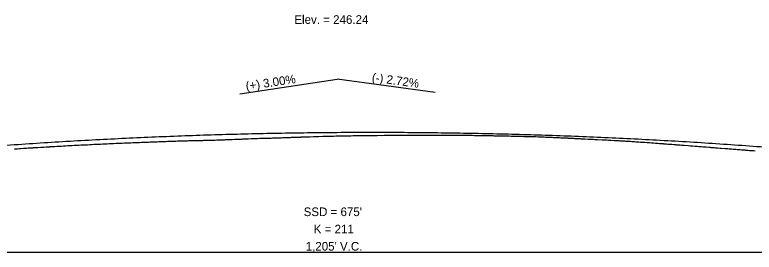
# Model space of a CAD drawing. Extents: x 1838386 to 1955906, y 719739 to 834437.
# Drawn here: x 1889991 to 1890591, y 826224 to 826417 of the extents above; entities that cross this region are included whole.
import ezdxf

# ---------------------------------------------------------------- set-up
doc = ezdxf.new("R2010")
doc.units = 0
for name, color, linetype in [('RD_DDB_GradeTX', 7, 'Continuous'), ('RD_DDB_Profile_EX', 7, 'Continuous'), ('RD_DDB_Profile_Lbl', 7, 'Continuous'), ('RD_DDB_Profile_PR', 7, 'Continuous'), ('RD_DDB_VCLbl', 7, 'Continuous')]:
    doc.layers.add(name, color=color, linetype=linetype)

msp = doc.modelspace()

# ---------------------------------------------------------------- linework, layer by layer
at = {"layer": 'RD_DDB_GradeTX'}
for p in [(1890173.96, 826352.46), (1890332.35, 826353.54)]:
    msp.add_line(p, (1890253.08, 826364.32), dxfattribs=at)
at = {"layer": 'RD_DDB_Profile_EX'}
for points in [[(1890027.2, 826310.09), (1890027.5, 826310.1), (1890029.04, 826310.16), (1890030.99, 826310.3), (1890032.55, 826310.36), (1890034.5, 826310.5), (1890036.11, 826310.56), (1890038, 826310.7), (1890039.63, 826310.75), (1890041.52, 826310.88), (1890043.18, 826310.92), (1890045.02, 826311.06), (1890046.7, 826311.11), (1890048.52, 826311.24), (1890050.24, 826311.28), (1890052.15, 826311.42), (1890053.78, 826311.47), (1890055.55, 826311.59), (1890057.31, 826311.63), (1890059.28, 826311.76), (1890060.85, 826311.8), (1890062.56, 826311.9), (1890064.38, 826311.96), (1890066.4, 826312.09), (1890067.92, 826312.13), (1890069.64, 826312.24), (1890071.45, 826312.28), (1890073.53, 826312.4), (1890075, 826312.44), (1890076.78, 826312.55), (1890078.52, 826312.58), (1890080.37, 826312.68), (1890080.67, 826312.7), (1890082.08, 826312.74), (1890083.6, 826312.82), (1890083.91, 826312.83), (1890085.59, 826312.87), (1890087.1, 826312.96), (1890087.44, 826312.97), (1890087.8, 826312.99), (1890089.15, 826313.02), (1890091.04, 826313.12), (1890092.66, 826313.16), (1890094.12, 826313.23), (1890094.51, 826313.24), (1890094.94, 826313.26), (1890096.24, 826313.3), (1890098.19, 826313.4), (1890099.74, 826313.43), (1890101.13, 826313.5), (1890101.58, 826313.51), (1890102.09, 826313.54), (1890103.32, 826313.57), (1890104.64, 826313.63), (1890105.34, 826313.66), (1890106.82, 826313.69), (1890108.14, 826313.76), (1890108.66, 826313.77), (1890109.23, 826313.8), (1890110.4, 826313.83), (1890111.66, 826313.89), (1890112.48, 826313.91), (1890113.89, 826313.94), (1890115.16, 826314), (1890116.35, 826314.04), (1890117.45, 826314.06), (1890118.65, 826314.12), (1890119.62, 826314.15), (1890120.96, 826314.18), (1890122.17, 826314.23), (1890123.45, 826314.28), (1890125.68, 826314.34), (1890126.75, 826314.37), (1890127.98, 826314.39), (1890129.19, 826314.44), (1890129.75, 826314.45), (1890130.34, 826314.48), (1890131.55, 826314.49), (1890132.7, 826314.55), (1890133.88, 826314.58), (1890135.05, 826314.59), (1890136.22, 826314.64), (1890136.85, 826314.64), (1890137.6, 826314.67), (1890138.7, 826314.68), (1890139.71, 826314.71), (1890141.01, 826314.73), (1890142.12, 826314.72), (1890143.25, 826314.76), (1890144, 826314.77), (1890144.83, 826314.81), (1890145.76, 826314.82), (1890146.73, 826314.86), (1890148.11, 826314.9), (1890150.27, 826314.96), (1890151.07, 826314.98), (1890151.96, 826315.01), (1890152.94, 826315.03), (1890153.73, 826315.06), (1890155.26, 826315.12), (1890156.02, 826315.13)], [(1890156.02, 826315.13), (1890157.23, 826315.18), (1890158.03, 826315.2), (1890158.85, 826315.24), (1890160.13, 826315.27), (1890160.77, 826315.29), (1890161.62, 826315.31), (1890162.42, 826315.36), (1890163.24, 826315.39), (1890164.26, 826315.43), (1890165.99, 826315.5), (1890166.32, 826315.51), (1890167.45, 826315.55), (1890167.77, 826315.56), (1890169.57, 826315.64), (1890170.49, 826315.67), (1890171.88, 826315.73), (1890172.88, 826315.75), (1890173.47, 826315.79), (1890174.93, 826315.85), (1890175.58, 826315.87), (1890176.34, 826315.91), (1890177.87, 826315.97), (1890178.2, 826315.98), (1890180.65, 826316.07), (1890183.14, 826316.18), (1890183.83, 826316.2), (1890185.6, 826316.25), (1890187.69, 826316.33), (1890188.03, 826316.34), (1890188.39, 826316.35), (1890190.34, 826316.43), (1890191.32, 826316.47), (1890193.15, 826316.53), (1890194.55, 826316.56), (1890196.08, 826316.59), (1890197.55, 826316.61), (1890198.13, 826316.64), (1890199.33, 826316.67), (1890200.49, 826316.71), (1890201.67, 826316.76), (1890202.83, 826316.8), (1890203.51, 826316.81), (1890205.23, 826316.89), (1890206.34, 826316.93), (1890207.75, 826316.95), (1890208.79, 826317.02), (1890209.84, 826317.05), (1890210.83, 826317.06), (1890212.38, 826317.13), (1890213.35, 826317.16), (1890214.96, 826317.18), (1890215.94, 826317.25), (1890216.86, 826317.28), (1890218.09, 826317.29), (1890219.52, 826317.38), (1890220.36, 826317.4), (1890223.08, 826317.49), (1890223.48, 826317.5), (1890223.87, 826317.51), (1890225.25, 826317.51), (1890226.65, 826317.61), (1890227.39, 826317.63), (1890230.2, 826317.71), (1890230.89, 826317.73), (1890233.78, 826317.82), (1890234.39, 826317.84), (1890237.34, 826317.94), (1890237.9, 826317.95), (1890241.4, 826318.05), (1890242.94, 826318.06), (1890244.91, 826318.16), (1890246.47, 826318.16), (1890248.42, 826318.25), (1890250.01, 826318.24), (1890251.92, 826318.32), (1890253.54, 826318.32), (1890255.43, 826318.41), (1890257.09, 826318.4), (1890258.94, 826318.48), (1890260.62, 826318.48), (1890262.44, 826318.55), (1890264.17, 826318.53), (1890265.96, 826318.61), (1890267.71, 826318.59), (1890269.5, 826318.66), (1890271.25, 826318.64), (1890273.05, 826318.71), (1890276.65, 826318.76), (1890278.26, 826318.74), (1890279.98, 826318.8), (1890281.8, 826318.76), (1890283.82, 826318.84), (1890285.36, 826318.81), (1890287.08, 826318.86), (1890288.89, 826318.83), (1890291, 826318.9), (1890292.46, 826318.87), (1890294.27, 826318.93), (1890295.92, 826318.89), (1890297.86, 826318.94)], [(1890297.86, 826318.94), (1890299.46, 826318.91), (1890301.46, 826318.97), (1890301.84, 826318.96), (1890303, 826318.93), (1890305, 826318.98), (1890306.51, 826318.94), (1890307.36, 826318.97), (1890308.57, 826318.99), (1890310.03, 826318.95), (1890311.47, 826319), (1890311.79, 826319), (1890312.12, 826319), (1890312.89, 826318.99), (1890313.55, 826318.97), (1890314.94, 826319.01), (1890315.31, 826319.01), (1890315.67, 826319.01), (1890317.01, 826318.98), (1890318.91, 826319.02), (1890320.5, 826318.98), (1890321.92, 826319.02), (1890322.33, 826319.02), (1890322.78, 826319.02), (1890324.05, 826318.98), (1890325.41, 826319.02), (1890326, 826319.02), (1890327.53, 826318.99), (1890328.91, 826319.02), (1890329.47, 826319.02), (1890329.87, 826319.02), (1890331.09, 826318.99), (1890332.42, 826319.02), (1890332.76, 826319.02), (1890333.08, 826319.02), (1890334.51, 826318.98), (1890335, 826318.99), (1890335.92, 826319.01), (1890336.26, 826319.01), (1890336.61, 826319.01), (1890338.02, 826318.98), (1890339.42, 826319), (1890339.79, 826319), (1890340.16, 826319), (1890340.52, 826319), (1890341.55, 826318.98), (1890342.93, 826319.01), (1890343.31, 826319), (1890343.68, 826319), (1890345.07, 826318.97), (1890346.05, 826318.99), (1890346.44, 826319), (1890346.83, 826318.99), (1890347.22, 826319), (1890348.53, 826318.96), (1890350.43, 826318.99), (1890351.58, 826318.96), (1890352.03, 826318.95), (1890353.48, 826318.97), (1890353.86, 826318.97), (1890354.28, 826318.97), (1890355.57, 826318.94), (1890357.47, 826318.95), (1890359.06, 826318.9), (1890360.52, 826318.91), (1890361.22, 826318.9), (1890362.63, 826318.88), (1890364.5, 826318.85), (1890366.04, 826318.79), (1890368.16, 826318.8), (1890369.56, 826318.74), (1890371.5, 826318.76), (1890373.07, 826318.69), (1890373.68, 826318.69), (1890374.66, 826318.69), (1890374.98, 826318.69), (1890378.49, 826318.63), (1890379.21, 826318.6), (1890380.03, 826318.57), (1890381.74, 826318.58), (1890383.54, 826318.51), (1890384.74, 826318.51), (1890385.47, 826318.51), (1890387.06, 826318.44), (1890388.85, 826318.43), (1890390.26, 826318.38), (1890390.58, 826318.36), (1890392.42, 826318.37), (1890394.09, 826318.29), (1890395.97, 826318.28), (1890399.1, 826318.19), (1890399.5, 826318.18), (1890401.32, 826318.12), (1890403.09, 826318.1), (1890404.56, 826318.04), (1890405.97, 826318.03), (1890406.31, 826318.01), (1890406.84, 826318), (1890408.08, 826317.93), (1890409.45, 826317.92), (1890409.83, 826317.9)], [(1890409.83, 826317.9), (1890410.23, 826317.9), (1890411.59, 826317.84), (1890412.37, 826317.82), (1890412.9, 826317.81), (1890413.35, 826317.79), (1890413.82, 826317.78), (1890416.38, 826317.69), (1890417.39, 826317.66), (1890417.9, 826317.63), (1890418.53, 826317.6), (1890419.53, 826317.58), (1890420.27, 826317.54), (1890420.98, 826317.51), (1890422.11, 826317.45), (1890423.42, 826317.41), (1890423.89, 826317.38), (1890424.56, 826317.37), (1890425.57, 826317.33), (1890426.44, 826317.3), (1890427.32, 826317.26), (1890428.15, 826317.23), (1890428.95, 826317.2), (1890430.05, 826317.16), (1890431.75, 826317.08), (1890432.58, 826317.03), (1890433.38, 826317.01), (1890434.48, 826316.95), (1890435.34, 826316.91), (1890436.11, 826316.87), (1890436.8, 826316.84), (1890438.97, 826316.76), (1890440, 826316.71), (1890440.31, 826316.69), (1890441.38, 826316.62), (1890442.55, 826316.58), (1890443.04, 826316.56), (1890443.46, 826316.54), (1890444.84, 826316.44), (1890445.53, 826316.41), (1890446.16, 826316.39), (1890447.16, 826316.34), (1890449.77, 826316.22), (1890450.09, 826316.2), (1890450.4, 826316.19), (1890451.06, 826316.15), (1890451.87, 826316.1), (1890453.39, 826316.05), (1890453.83, 826316.02), (1890456.59, 826315.87), (1890457.35, 826315.83), (1890458.87, 826315.73), (1890460.63, 826315.68), (1890462.11, 826315.61), (1890464.26, 826315.5), (1890467.88, 826315.31), (1890469.32, 826315.21), (1890470.65, 826315.16), (1890471.09, 826315.13), (1890471.51, 826315.11), (1890473.17, 826315.02), (1890474.2, 826314.97), (1890474.63, 826314.94), (1890475.15, 826314.92), (1890477.61, 826314.79), (1890478.8, 826314.72), (1890480.79, 826314.61), (1890481.63, 826314.55), (1890482.4, 826314.51), (1890483.4, 826314.44), (1890484.28, 826314.4), (1890485.14, 826314.34), (1890486.12, 826314.29), (1890486.91, 826314.24), (1890487.75, 826314.2), (1890488.73, 826314.12), (1890489.75, 826314.07), (1890490.93, 826314), (1890492.19, 826313.89), (1890493.4, 826313.85), (1890493.92, 826313.82), (1890494.33, 826313.79), (1890495.27, 826313.71), (1890495.61, 826313.67), (1890497.06, 826313.61), (1890497.48, 826313.59), (1890497.84, 826313.56), (1890499.12, 826313.43), (1890501.09, 826313.33), (1890502.7, 826313.18), (1890504.39, 826313.11), (1890506.33, 826312.91), (1890508.07, 826312.83), (1890509.63, 826312.67), (1890511.26, 826312.58), (1890511.85, 826312.53), (1890513.14, 826312.41), (1890514.43, 826312.34), (1890514.93, 826312.3), (1890515.4, 826312.27), (1890517.38, 826312.12)], [(1889991.23, 826307.87), (1889991.85, 826307.92), (1889992.42, 826307.95), (1889993.7, 826308.01), (1889995.12, 826308.13), (1889995.51, 826308.16), (1889995.93, 826308.18), (1889998.36, 826308.35), (1889998.93, 826308.39), (1889999.44, 826308.42), (1890000.77, 826308.47), (1890002.25, 826308.6), (1890002.58, 826308.63), (1890002.94, 826308.65), (1890005.5, 826308.8), (1890006, 826308.83), (1890006.45, 826308.86), (1890007.84, 826308.92), (1890009.95, 826309.08), (1890012.62, 826309.23), (1890013.06, 826309.26), (1890013.46, 826309.28), (1890014.9, 826309.34), (1890016.96, 826309.5), (1890018.36, 826309.56), (1890019.73, 826309.66), (1890020.12, 826309.69), (1890020.48, 826309.71), (1890021.97, 826309.77), (1890023.99, 826309.91), (1890025.46, 826309.96), (1890026.86, 826310.06), (1890027.2, 826310.09)], [(1890517.38, 826312.12), (1890517.76, 826312.09), (1890518.36, 826312.03), (1890519.1, 826311.98), (1890520.23, 826311.87), (1890521.23, 826311.82), (1890521.93, 826311.75), (1890522.91, 826311.7), (1890523.66, 826311.63), (1890524.56, 826311.57), (1890526.5, 826311.42), (1890527.15, 826311.37), (1890527.76, 826311.33), (1890528.43, 826311.26), (1890528.98, 826311.2), (1890530.15, 826311.14), (1890530.71, 826311.1), (1890531.16, 826311.07), (1890532.41, 826310.94), (1890533.96, 826310.86), (1890534.29, 826310.83), (1890534.63, 826310.81), (1890537.89, 826310.57), (1890539.49, 826310.4), (1890541.28, 826310.29), (1890543.06, 826310.11), (1890544.42, 826310.04), (1890545.05, 826310), (1890546.51, 826309.86), (1890547.9, 826309.77), (1890548.25, 826309.73), (1890548.65, 826309.71), (1890549.95, 826309.59), (1890550.54, 826309.56), (1890551.23, 826309.51), (1890552.44, 826309.42), (1890554.42, 826309.25), (1890555.29, 826309.17), (1890556.15, 826309.12), (1890557.76, 826309), (1890558.74, 826308.89), (1890559.86, 826308.83), (1890561.15, 826308.73), (1890561.59, 826308.7), (1890563.61, 826308.55), (1890564.08, 826308.51), (1890564.46, 826308.48), (1890567.72, 826308.22), (1890569.89, 826308.06), (1890571.08, 826307.97), (1890572.88, 826307.78), (1890574.23, 826307.7), (1890574.89, 826307.65), (1890576.33, 826307.52), (1890577.64, 826307.44), (1890578.17, 826307.4), (1890578.55, 826307.38), (1890579.8, 826307.26), (1890580.98, 826307.18), (1890582.29, 826307.08), (1890583.26, 826307), (1890583.7, 826306.97), (1890584.2, 826306.93), (1890585.15, 826306.84), (1890586.13, 826306.78), (1890587.43, 826306.68), (1890588.61, 826306.56), (1890589.23, 826306.53), (1890589.81, 826306.49), (1890590.81, 826306.42), (1890592.08, 826306.29)]]:
    msp.add_lwpolyline(points, dxfattribs=at)
at = {"layer": 'RD_DDB_Profile_PR'}
msp.add_spline([(1889650.58, 826274.06), (1889674.68, 826277.6), (1889698.78, 826281), (1889722.88, 826284.27), (1889746.98, 826287.4), (1889771.08, 826290.39), (1889795.18, 826293.24), (1889819.28, 826295.95), (1889843.38, 826298.53), (1889867.48, 826300.97), (1889891.58, 826303.27), (1889915.68, 826305.44), (1889939.78, 826307.47), (1889963.88, 826309.35), (1889987.98, 826311.11), (1890012.08, 826312.72), (1890036.18, 826314.19), (1890060.28, 826315.53), (1890084.38, 826316.73), (1890108.48, 826317.79), (1890132.58, 826318.72), (1890156.68, 826319.51), (1890180.78, 826320.16), (1890204.88, 826320.67), (1890228.98, 826321.04), (1890253.08, 826321.28), (1890277.18, 826321.38), (1890301.28, 826321.34), (1890325.38, 826321.16), (1890349.48, 826320.85), (1890373.58, 826320.39), (1890397.68, 826319.8), (1890421.78, 826319.07), (1890445.88, 826318.21), (1890469.98, 826317.21), (1890494.08, 826316.06), (1890518.18, 826314.79), (1890542.28, 826313.37), (1890566.38, 826311.81), (1890590.48, 826310.12), (1890614.58, 826308.29), (1890638.68, 826306.33), (1890662.78, 826304.22), (1890686.88, 826301.98), (1890710.98, 826299.6), (1890735.08, 826297.08), (1890759.18, 826294.42), (1890783.28, 826291.63), (1890807.38, 826288.7), (1890831.48, 826285.63), (1890855.58, 826282.42)], degree=3, dxfattribs=at)
at = {"layer": 'RD_DDB_VCLbl'}
msp.add_line((1889650.58, 826224.06), (1890855.58, 826224.06), dxfattribs=at)

# ---------------------------------------------------------------- texts
at = {"layer": 'RD_DDB_GradeTX'}
for s, rotation, p in [('(+) 3.00%', 8.52013, (1890179.28, 826355.28)), ('(-) 2.72%', 352.25935, (1890280.78, 826362.57))]:
    msp.add_text(s, height=7, rotation=rotation, dxfattribs=at).set_placement(p)
at = {"layer": 'RD_DDB_Profile_Lbl'}
msp.add_text('Elev. = 246.24', height=7, dxfattribs=at).set_placement((1890218.22, 826409.32))
at = {"layer": 'RD_DDB_VCLbl'}
for s, p in [("SSD = 675'", (1890225.77, 826253.31)), ('K = 211', (1890233.95, 826239.31)), ("1,205' V.C.", (1890227.42, 826225.31))]:
    msp.add_text(s, height=7, dxfattribs=at).set_placement(p)

doc.saveas('drawing.dxf')
